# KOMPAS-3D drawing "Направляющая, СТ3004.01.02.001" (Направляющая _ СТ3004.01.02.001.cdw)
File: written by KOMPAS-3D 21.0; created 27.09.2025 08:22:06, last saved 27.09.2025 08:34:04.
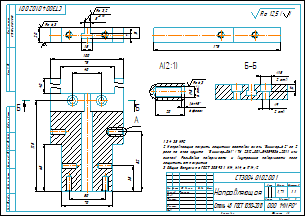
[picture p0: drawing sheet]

Sheet 1: A3, landscape

Document properties: Полное имя файла: C:\Users\Lutik\Yandex.Disk\Документы\Новая папка\Стапель №2\Стапель _ СТ3004.00.00.000\Опора _ СТ3004.01.00.000\2D\Кронштейн _ СТ3004.01.02.000\Направляющая _ СТ3004.01.02.001.cdw; Знак неуказанной шероховатости: 4; Параметр неуказанной шероховатости: Ra 12,5; Масса: 1.713262

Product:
- Part/product: Направляющая  | designation СТ3004.01.02.001
    Материал: Сталь 45  ГОСТ 1050-2013 (density 7810 kg/m3)
    Масса: 1.713262

Title block, sheet 1: Наименование: Направляющая; designation: СТ3004.01.02.001; Материал: Сталь 45  ГОСТ 1050-2013; Масса: 1,71; Количество листов документа: 1; organisation: ООО "МИРО"; Форматы листов документа: A3; Разработал: Тимонин

Views: Вид 1, Слева, Проекционный вид 2, Местный разрез 1, Проекционный вид 3, Разрез А-А, Выносной элемент 5, Разрез Б-Б, Выносной элемент А, Выносной элемент
Referenced files in C:\Users\Lutik\Yandex.Disk\Документы\Новая папка\Стапель №2\Стапель _ СТ3004.00.00.000\Опора _ СТ3004.01.00.000\3D\Кронштейн _ СТ3004.01.02.000\: Направляющая _ СТ3004.01.02.001.m3d
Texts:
  Ra 3,2
  Ra 6,3
  Ra 12,5
  Ra 12,5 ( )
  СТ3004.01.02.000
  СТ3004.01.02.001 Направляющая
Dimensions and other numbers on the sheet: 8; 15; 7; 20; 40; 75; 100; 65; 70; 50; 35; 82; 125; 175; 10; 2 отв.; 9; 6 отв.; 1,6; 6 фасок; 1:1; 1; 1,71

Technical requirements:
  34...38 HRC.
  Направляющию покрыть защитным составом эмаль "Виникор-62" за 2
  раза по слою грунта  "Виникор-061" (ТУ 2312-001-54359536-2011 или
  аналог). Резьбовые поверхности и внутренние поверхности паза
  защитить от покрытия.
  Общие допуски по ГОСТ 30893.1: Н14, h14, ± IT14/2.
